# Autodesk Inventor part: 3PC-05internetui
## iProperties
Created: 2010-11
Part Number: 3PC-05internetui
Document SubType Name: Modeling
Designer: Darius
Author: Darius
Translation Standard: STEP AP203
File Name: 3PC-05.STEP
Preprocessor: SolidWorks 2003240
Postprocessor: Build: 272, Release: 10 SP3a - Date: Thu 12/15/2005
Sent Units: MILLIMETERS
Uncertainty: 1e-05
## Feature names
1. Base1
